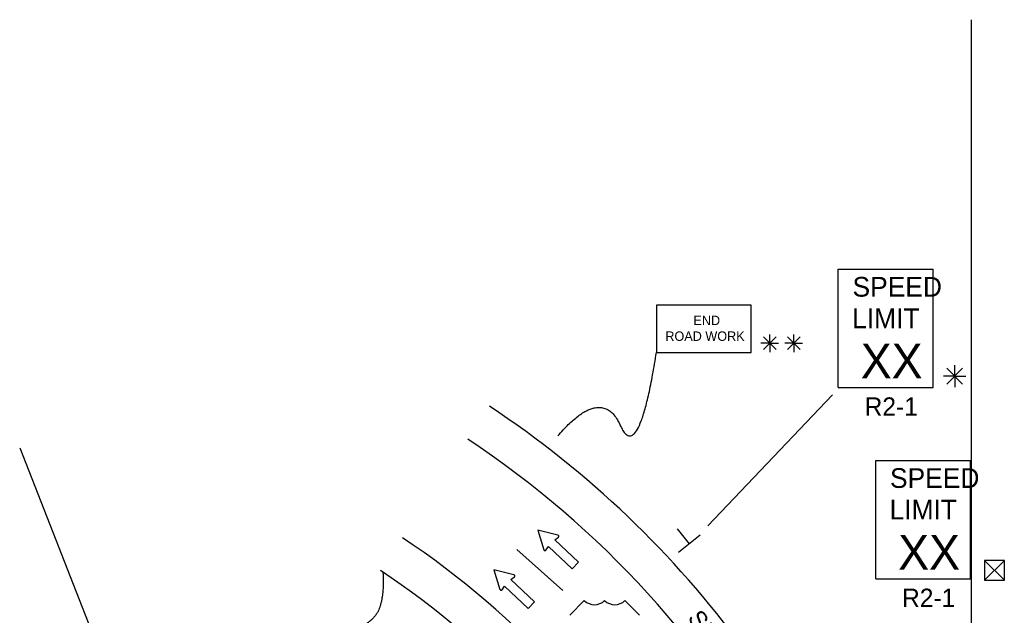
# Model space of a CAD drawing. Extents: x 16512 to 19512, y 5761 to 6974.
# Drawn here: x 16595 to 16998.2, y 6732.7 to 6974.1 of the extents above; entities that cross this region are included whole.
import ezdxf

# ---------------------------------------------------------------- set-up
doc = ezdxf.new("R2010")
doc.units = 0
for name, color, linetype in [('ALI_LEGAL_EX', 7, 'Continuous'), ('MT_SCRATCH_LEVEL_E', 7, 'Continuous'), ('PAVT_EDGE_EX', 7, 'Continuous'), ('TRAFFIC_SIGNS_PR', 7, 'Continuous'), ('TYPICAL_EX', 7, 'Continuous'), ('TYPICAL_TEXT_DIMEN_PR', 7, 'Continuous')]:
    doc.layers.add(name, color=color, linetype=linetype)

msp = doc.modelspace()

# ---------------------------------------------------------------- linework, layer by layer
at = {"layer": 'ALI_LEGAL_EX'}
for p, q in [((16980.68, 6974.12), (16980.68, 6155.98)), ((16980.68, 6922.21), (16980.68, 6058.3)), ((16594.98, 6800.51), (16817, 6232.14))]:
    msp.add_line(p, q, dxfattribs=at)
msp.add_lwpolyline([(16815.12, 6742.72), (16796.45, 6759.35)], dxfattribs=at)
at = {"layer": 'MT_SCRATCH_LEVEL_E'}
for p, q in [((16813.17, 6765.15), (16805.06, 6767.11)), ((16805.06, 6767.11), (16807.49, 6759.15)), ((16811.89, 6763.25), (16813.34, 6764.33)), ((16821.51, 6754.14), (16811.89, 6763.25)), ((16808.32, 6759.03), (16809.31, 6760.54)), ((16809.31, 6760.54), (16818.94, 6751.42)), ((16818.94, 6751.42), (16821.51, 6754.14)), ((16795.35, 6749.07), (16787.24, 6751.04)), ((16787.24, 6751.04), (16789.67, 6743.07)), ((16794.07, 6747.18), (16795.52, 6748.25)), ((16803.69, 6738.06), (16794.07, 6747.18)), ((16790.5, 6742.95), (16791.5, 6744.46)), ((16791.5, 6744.46), (16801.12, 6735.34)), ((16801.12, 6735.34), (16803.69, 6738.06))]:
    msp.add_line(p, q, dxfattribs=at)
for centre, start, end in [((16813.05, 6764.7), 306.594, 76.331), ((16807.94, 6759.29), 196.9827, 326.5217), ((16795.23, 6748.62), 306.594, 76.331), ((16790.12, 6743.21), 196.9827, 326.5217)]:
    msp.add_arc(centre, 0.463, start, end, dxfattribs=at)
at = {"layer": 'PAVT_EDGE_EX'}
for centre, radius, start, end in [((16562.45, 6480.53), 404, 15.917, 56.5037), ((16562.45, 6480.53), 388, 0, 56.5037), ((17314.45, 6480.53), 380, 121.9327, 163.0483), ((17314.45, 6480.53), 364, 121.9327, 180), ((16562.45, 6480.53), 340, 0, 56.5037), ((16562.45, 6480.53), 324, 0, 56.5037)]:
    msp.add_arc(centre, radius, start, end, dxfattribs=at)
at = {"layer": 'TRAFFIC_SIGNS_PR'}
for p, q in [((16926.87, 6873), (16965.27, 6873)), ((16926.87, 6825), (16926.87, 6873)), ((16965.27, 6825), (16965.27, 6873)), ((16926.87, 6825), (16965.27, 6825)), ((16942.04, 6795.43), (16980.44, 6795.43)), ((16942.04, 6747.43), (16942.04, 6795.43)), ((16980.44, 6747.43), (16980.44, 6795.43)), ((16942.04, 6747.43), (16980.44, 6747.43))]:
    msp.add_line(p, q, dxfattribs=at)
msp.add_lwpolyline([(16853.11, 6839.18), (16891.51, 6839.18), (16891.51, 6858.38), (16853.11, 6858.38)], close=True, dxfattribs=at)
at = {"layer": 'TYPICAL_EX'}
for p, q in [((16817.96, 6732.69), (16823.85, 6738.58)), ((16846.26, 6732.69), (16840.36, 6738.58))]:
    msp.add_line(p, q, dxfattribs=at)
for centre in [(16827.98, 6742.88), (16836.23, 6742.88)]:
    msp.add_arc(centre, 5.96, 226.1404, 313.8596, dxfattribs=at)
at = {"layer": 'TYPICAL_TEXT_DIMEN_PR'}
for p, q in [((16899.06, 6843), (16899.06, 6846.57)), ((16908.8, 6843), (16908.8, 6846.57)), ((16899.06, 6843), (16895.43, 6843)), ((16896.51, 6845.55), (16901.61, 6840.45)), ((16901.61, 6845.55), (16896.51, 6840.45)), ((16899.06, 6843), (16901.61, 6843)), ((16899.06, 6843), (16902.64, 6843)), ((16899.06, 6843), (16899.06, 6839.4)), ((16908.8, 6843), (16905.18, 6843)), ((16906.25, 6845.55), (16911.35, 6840.45)), ((16911.35, 6845.55), (16906.25, 6840.45)), ((16908.8, 6843), (16911.35, 6843)), ((16908.8, 6843), (16912.38, 6843)), ((16908.8, 6843), (16908.8, 6839.4)), ((16974.05, 6829.62), (16974.05, 6834.07)), ((16970.87, 6832.8), (16977.24, 6826.43)), ((16977.24, 6832.8), (16970.87, 6826.43)), ((16974.05, 6829.62), (16969.52, 6829.62)), ((16974.05, 6829.62), (16977.24, 6829.62)), ((16974.05, 6829.62), (16978.53, 6829.62)), ((16974.05, 6829.62), (16974.05, 6825.12)), ((16924.47, 6822.03), (16873.98, 6768.85)), ((16866.48, 6761.57), (16861.61, 6767.65)), ((16870.87, 6765.09), (16862.09, 6758.06)), ((16986.19, 6746.9), (16994.19, 6754.9)), ((16986.2, 6754.9), (16994.19, 6746.9))]:
    msp.add_line(p, q, dxfattribs=at)
msp.add_lwpolyline([(16986.2, 6754.9), (16986.19, 6746.9), (16994.19, 6746.9), (16994.19, 6754.9)], close=True, dxfattribs=at)
for points in [[(16813.09, 6805.35), (16830.93, 6826.13), (16845.88, 6793.26), (16853.11, 6839.18)], [(16742.2, 6749.78), (16742.81, 6740.39), (16738.12, 6729.17), (16727.65, 6725.49)]]:
    msp.add_open_spline(points, degree=2, dxfattribs=at)

# ---------------------------------------------------------------- texts
at = {"layer": 'TRAFFIC_SIGNS_PR'}
for s, height, p in [('SPEED', 8, (16932.63, 6861.86)), ('END', 3.831, (16868.11, 6850.31)), ('LIMIT', 8, (16932.47, 6849.06)), ('ROAD WORK', 3.831, (16856.72, 6843.92)), ('XX', 14.031, (16935.98, 6828.76)), ('R2-1', 7.44, (16937.54, 6813.56)), ('SPEED', 8, (16947.81, 6784.29)), ('LIMIT', 8, (16947.65, 6771.49)), ('XX', 14.031, (16951.16, 6751.19)), ('R2-1', 7.44, (16952.72, 6735.99))]:
    msp.add_text(s, height=height, dxfattribs=at).set_placement(p)
at = {"layer": 'TYPICAL_TEXT_DIMEN_PR'}
msp.add_text('SHOULDER', height=7, rotation=305.9489, dxfattribs=at).set_placement((16865.49, 6731.47))

doc.saveas('drawing.dxf')
